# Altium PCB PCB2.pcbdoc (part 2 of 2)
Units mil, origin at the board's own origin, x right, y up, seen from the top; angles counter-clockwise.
Board outline 2299 x 1559.01 mil, 4 copper layers (Top Layer, Inner1, Inner2, Bottom Layer); 35 components, 78 nets, 930 pads, 283 vias.
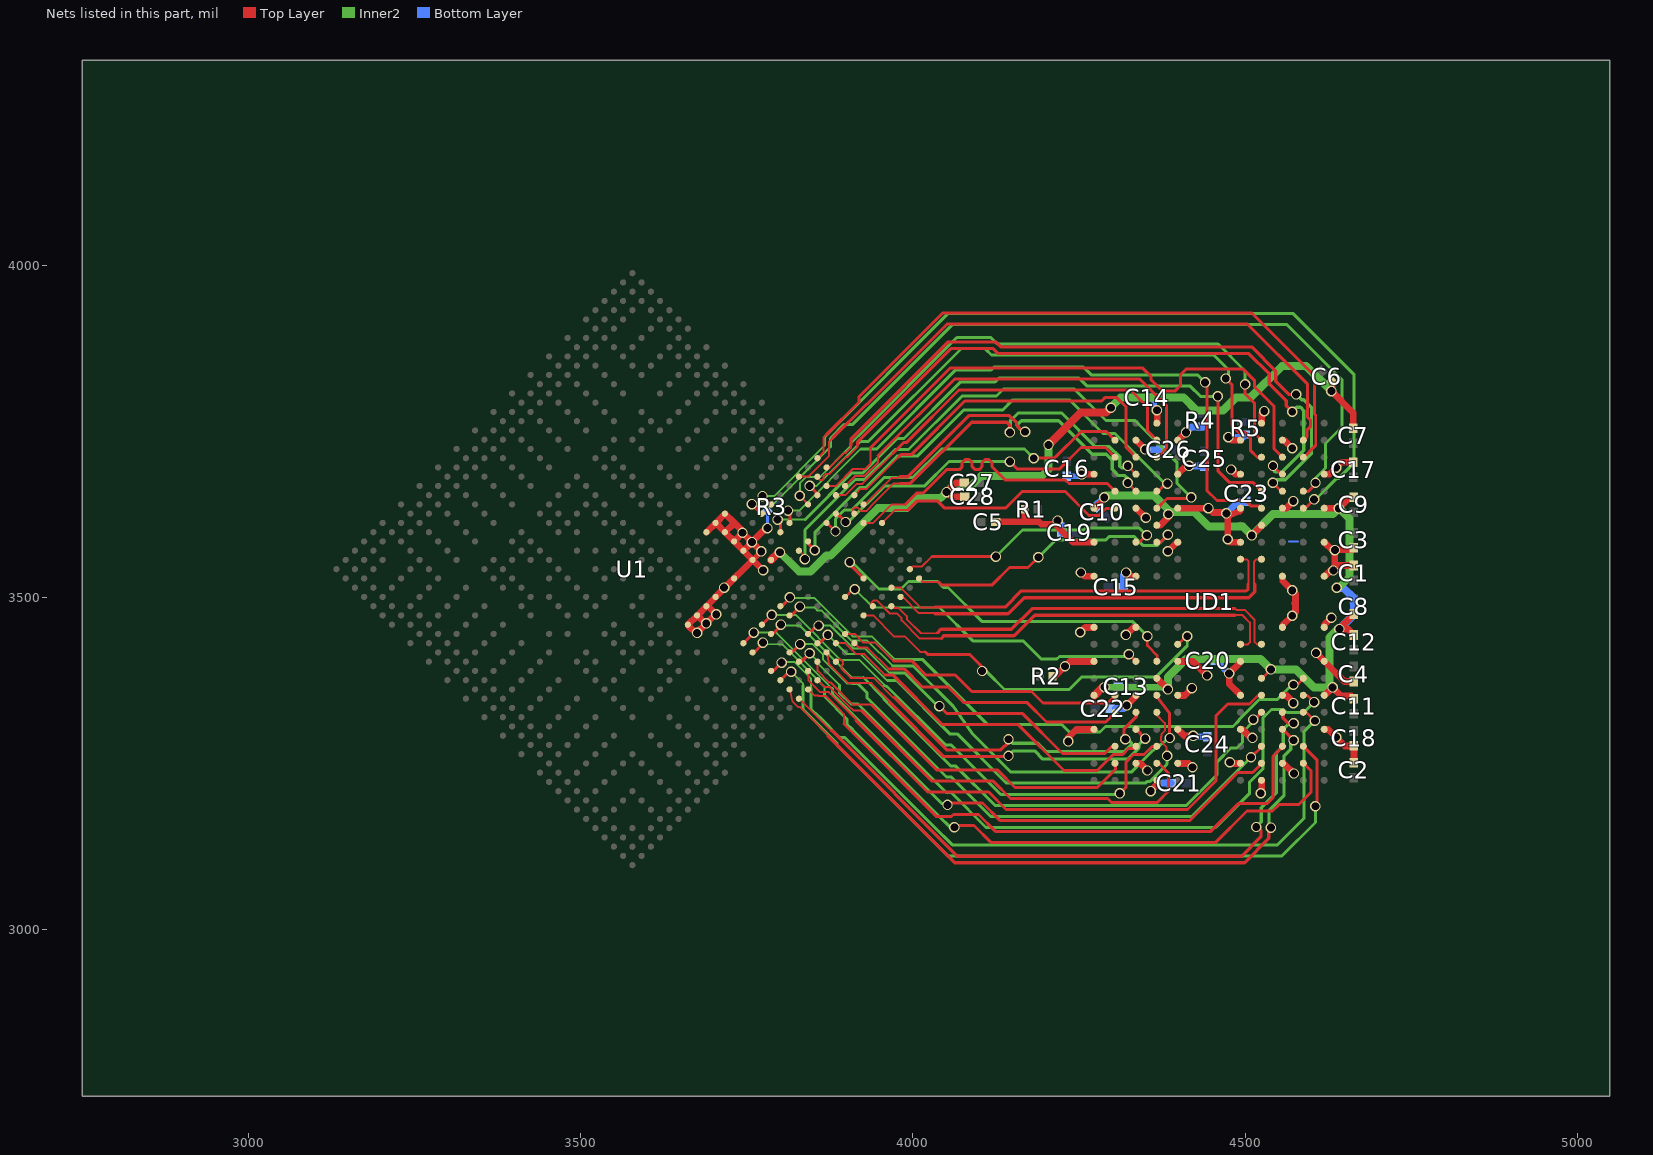
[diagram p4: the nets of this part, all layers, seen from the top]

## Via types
v1: diameter 15.75, hole 11.81, Top Layer to Bottom Layer, 283 vias

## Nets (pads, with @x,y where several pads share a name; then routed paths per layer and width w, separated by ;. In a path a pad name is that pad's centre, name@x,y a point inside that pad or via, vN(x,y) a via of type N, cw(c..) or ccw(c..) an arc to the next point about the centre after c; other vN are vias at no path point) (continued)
SCKE1-B: U1.AM27 UD1.P5 | length 596.8
  Top Layer w3: U1.AM27@3926.31,3473.4 3940.27,3473.4 3971.67,3442 3987.87,3442 4011.15,3418.72 4018.57,3418.72
  Top Layer w4: UD1.P5@4399.28,3429.75 4411.53,3442 v1(4413.08,3442)
  Top Layer w4.5: 4018.57,3418.72 4022.46,3414.83 4085.25,3414.83 4104.4,3395.68 v1(4104.4,3389.75)
  Inner2 w4.5: v1(4104.4,3389.75) 4105.35,3388.8 4111.28,3388.8 4138.08,3362 4235.59,3362 4254.59,3381 4366.35,3381 4413.08,3427.73 v1(4413.08,3442)
SCKN-A: U1.AN30 UD1.J9 | length 615.6
  Top Layer w3: U1.AN30@3981.99,3501.25 3984.6,3501.25 4008.85,3477 4032.83,3477 4033.83,3476 ; 4514.51,3520.25 4514.51,3521 4513.51,3522 4513.51,3554.43 4516.79,3557.71 UD1.J9@4525.26,3557.71
  Top Layer w5: 4033.83,3476 4143.41,3476 4167.58,3500.17 4505.66,3500.17 4514.51,3509.02 4514.51,3520.25
SCKN-B: U1.AN29 UD1.P9 | length 634
  Top Layer w3: U1.AN29@3968.06,3487.31 3970.88,3484.49 3979.12,3484.49 3991.12,3472.49 3991.12,3467.9 4012.41,3446.58 4036.41,3446.58 4037.41,3447.58 ; 4485.07,3483.76 4485.45,3483.76 4487.45,3481.76 4499.52,3481.76 4514,3467.28 4514,3434.06 4518.31,3429.75 UD1.P9@4525.26,3429.75
  Top Layer w5: 4037.41,3447.58 4042.41,3452.58 4148.28,3452.58 4179.46,3483.76 4485.07,3483.76
SCKP-A: U1.AM30 UD1.J8 | length 615.5
  Top Layer w3: U1.AM30@3968.07,3515.16 3982.01,3515.16 4012.17,3485 4032.45,3485 4033.45,3486 4033.83,3486 ; UD1.J8@4493.76,3557.71 4502.51,3557.71 4505.51,3554.71 4505.51,3522 4504.51,3521 4504.51,3520.25
  Top Layer w5: 4033.83,3486 4139.26,3486 4163.43,3510.17 4501.51,3510.17 4504.51,3513.17 4504.51,3520.25
SCKP-B: U1.AM28 UD1.P8 | length 666.5
  Top Layer w3: U1.AM28@3940.23,3487.32 3938.08,3489.46 3938.08,3492.98 3941.08,3495.98 3945.52,3495.98 3965,3476.49 3975.8,3476.49 3983.12,3469.17 3983.12,3466 4010.5,3438.58 4042.56,3438.58 ; 4485.07,3473.76 4496.2,3473.76 4507.31,3462.65 4507.31,3432.75 4504.31,3429.75 UD1.P8@4493.76,3429.75
  Top Layer w5: 4042.56,3438.58 4046.56,3442.58 4152.43,3442.58 4183.61,3473.76 4485.07,3473.76
SCS0-A: U1.AN32 UD1.H4 | length 442.4
  Top Layer w3: U1.AN32@4009.82,3529.08 4015.18,3523.72 4039.28,3523.72
  Top Layer w4.5: 4039.28,3523.72 4044,3519 4119.01,3519 4145.51,3545.5 4173.58,3545.5 v1(4189.08,3561) ; UD1.H4@4367.78,3583.3 4372.3,3583.3 4383.73,3594.73 v1(4384,3594.73)
  Inner2 w4.5: v1(4189.08,3561) 4214.98,3586.9 4290.49,3586.9 4296.09,3592.5 4332.69,3592.5 4346.89,3578.3 4367.57,3578.3 v1(4384,3594.73)
SCS0-B: U1.AK29 UD1.R4 | length 580.8
  Top Layer w4: v1(4353.08,3442) 4353.08,3428 4367.78,3413.3 UD1.R4@4367.78,3404.16
  Top Layer w4.5: v1(3905.09,3553.58) 3905.09,3550.3 U1.AK29@3926.31,3529.08
  Inner2 w4.5: v1(3905.09,3553.58) 3908.8,3549.9 3912.1,3549.9 3949,3513 3982.2,3513 3993.5,3524.3 4037.21,3524.3 4045.91,3515.6 4052.99,3515.6 4103.97,3464.62 4330.46,3464.62 v1(4353.08,3442)
SCS1-A: U1.AM32 UD1.H3 | length 407.1
  Top Layer w3: U1.AM32@3995.91,3543 4000.01,3547.09 4013.89,3547.09 4028.8,3562
  Top Layer w4.5: 4028.8,3562 v1(4125.08,3562) ; UD1.H3@4336.28,3583.3 4340.4,3583.3 4350.1,3593 4350.87,3593 4352.02,3594.15 v1(4352.27,3594.15)
  Inner2 w4.5: v1(4125.08,3562) 4164.99,3601.91 4257.01,3601.91 4260.2,3605.1 4340.9,3605.1 4351.85,3594.15 v1(4352.27,3594.15)
SCS1-B: U1.AK27 UD1.R3 | length 493.7
  Top Layer w4: U1.AK27@3898.47,3501.24 3910.13,3512.9 v1(3912.64,3512.9)
  Top Layer w4.5: v1(4325.36,3415.07) UD1.R3@4336.27,3404.16
  Inner2 w3: v1(3912.64,3512.9) 3940.13,3485.41 4040.09,3485.41
  Inner2 w4.5: 4040.09,3485.41 4090.4,3435.1 4165.9,3435.1 4193.25,3407.75 4216.85,3407.75 4220.84,3411.74 4322.03,3411.74 v1(4325.36,3415.07)
SDQ0: U1.AE28 UD1.E4 | length 729.7
  Top Layer w4.5: U1.AE28@3842.79,3584.76 3842.79,3581.33 v1(3852.53,3571.59) ; UD1.E4@4367.78,3660.07 4369.15,3660.07 4380.08,3671 4382.08,3671 4382.88,3671.8 v1(4383.13,3671.8)
  Inner2 w4.5: v1(3852.53,3571.59) 3852.53,3598.29 3920.24,3666 3929.08,3666 3976.08,3713 4006.9,3713 4076.56,3782.66 4135.44,3782.66 4150.58,3797.8 4235.71,3797.8 4286.21,3747.3 4304.22,3747.3 4328.48,3723.04 4328.48,3722.69 4379.37,3671.8 v1(4383.13,3671.8)
SDQ1: U1.AE27 UD1.F4 | length 873.7
  Top Layer w3: U1.AE27@3828.87,3570.84 3837.68,3562.03 v1(3837.68,3558.15)
  Top Layer w4.5: UD1.F4@4367.78,3634.48 4367.78,3634.7 4382.58,3649.5 4413.58,3649.5 4414.08,3650 4418,3650 v1(4419,3651)
  Inner2 w4.5: v1(3837.68,3558.15) 3837.68,3602.15 3913.81,3678.28 3928.36,3678.28 3973.08,3723 3993.56,3723 4074.26,3803.7 4126.04,3803.7 4136.64,3814.3 4243.07,3814.3 4290.62,3766.75 4334.49,3766.75 4398,3703.24 4398,3672 v1(4419,3651)
SDQ2: U1.AG32 UD1.E2 | length 464.8
  Top Layer w3: U1.AG32@3926.31,3612.6 3940.2,3612.6 3967.6,3640 3988.2,3640
  Top Layer w4.5: 3988.2,3640 4006.2,3658 4016.08,3658 4050.92,3692.84 4069.85,3692.84 4074.35,3697.34 4074.35,3703.5 4078.85,3708 4084.85,3708 4089.35,3703.5 4089.35,3697.34 4093.85,3692.84 4099.85,3692.84 4104.35,3697.34 4104.35,3703.5 4108.85,3708 4114.85,3708 4119.35,3703.5 4119.35,3697.34 4139.69,3677 4230,3677 4235,3672 4292.86,3672 UD1.E2@4304.79,3660.07
SDQ3: U1.AH33 UD1.F2 | length 398.6
  Top Layer w3: U1.AH33@3954.15,3612.59 3973.84,3632.28 3993.24,3632.28
  Top Layer w4.5: 3993.24,3632.28 4006.92,3645.96 4036.84,3645.96 4047.43,3635.37 4140.46,3635.37 4165.3,3660.21 4229.03,3660.21 4265.33,3623.91 4279.99,3623.91 4290.56,3634.48 UD1.F2@4304.79,3634.48
SDQ4: U1.AE30 UD1.B2 | length 529.9
  Top Layer w4.5: U1.AE30@3870.63,3612.6 3870.89,3612.6 v1(3883.72,3599.77) ; v1(4182.08,3710) 4213.08,3710 4253.08,3750 4291.63,3750 UD1.B2@4304.79,3736.84
  Inner2 w4.5: v1(3883.72,3599.77) 3883.72,3618.87 3896.95,3632.1 3908.11,3632.1 3956.73,3680.72 3999.81,3680.72 4043.09,3724 4168.08,3724 v1(4182.08,3710)
SDQ5: U1.AD32 UD1.B4 | length 600.8
  Top Layer w3: U1.AD32@3884.55,3654.36 3898.5,3654.36 3915.43,3671.29 3924.24,3671.29 3969.95,3717
  Top Layer w4.5: 3969.95,3717 3986.95,3734 3991.08,3734 4069.58,3812.5 4327.5,3812.5 4353,3787 4353,3751.62 UD1.B4@4367.78,3736.84
SDQ6: U1.AE31 UD1.C2 | length 487.4
  Top Layer w4.5: U1.AE31@3884.55,3626.52 3886.48,3626.52 v1(3899,3614) ; v1(4146.08,3705) 4157.58,3693.5 4220.57,3693.5 4253.03,3725.96 4290.08,3725.96 UD1.C2@4304.79,3711.25
  Inner2 w4.5: v1(3899,3614) 3903,3614 3957,3668 4017.4,3668 4054.4,3705 v1(4146.08,3705)
SDQ7: U1.AD33 UD1.C4 | length 656.3
  Top Layer w3: U1.AD33@3898.47,3668.27 3913.43,3683.22 3927.22,3683.22 3947.8,3703.8 3947.8,3714.06
  Top Layer w4.5: 3947.8,3714.06 4062.74,3829 4342,3829 4382,3789 4382,3725.47 UD1.C4@4367.78,3711.25
SDQ8: U1.AC27 UD1.E9 | length 973.9
  Top Layer w4.5: v1(3796.67,3617.55) 3801.03,3613.19 U1.AC27@3801.03,3598.68 ; v1(4459,3803) 4459,3691 4476.89,3673.11 4512.22,3673.11 UD1.E9@4525.26,3660.07
  Inner2 w3: v1(3796.67,3617.55) 3837.63,3617.55
  Inner2 w4.5: 3837.63,3617.55 3908.08,3688 3925,3688 3976.53,3739.53 3986.75,3739.53 4072.22,3825 4124,3825 4129.8,3830.8 4249.91,3830.8 4261.71,3819 4417,3819 4417.55,3818.45 4417.78,3818.45 4433.23,3803 v1(4459,3803)
SDQ9: U1.AC28 UD1.F9 | length 1004.1
  Top Layer w4.5: v1(3812.19,3631.19) 3814.95,3628.43 U1.AC28@3814.95,3612.6 ; v1(4440,3824) 4442.58,3821.42 4442.58,3661.51 4457.77,3646.32 4500.3,3646.32 4508.62,3638 4521.74,3638 UD1.F9@4525.26,3634.48
  Inner2 w3: v1(3812.19,3631.19) 3829.09,3631.19 3921.9,3724
  Inner2 w4.5: 3921.9,3724 3945.81,3724 4064.81,3843 4118,3843 4122.3,3847.3 4256.75,3847.3 4268.55,3835.5 4428.5,3835.5 v1(4440,3824)
SDQ10: U1.AC30 UD1.B9 | length 936.1
  Top Layer w3: v1(3829.98,3653.51) 3842.79,3640.7 U1.AC30@3842.79,3640.44
  Top Layer w4.5: v1(4500.08,3821) 4500.08,3807 4514.08,3793 4514.08,3748.02 UD1.B9@4525.26,3736.84
  Inner2 w3: v1(3829.98,3653.51) 3829.98,3672.41 3839.57,3682 3860.51,3682 3906.26,3727.74 3906.26,3731.55 3919.08,3744.37
  Inner2 w4.5: 3919.08,3744.37 4066.31,3891.6 4117.4,3891.6 4127.25,3881.75 4459.67,3881.75 4500.08,3841.34 v1(4500.08,3821)
SDQ11: U1.AC31 UD1.C9 | length 913.6
  Top Layer w4.5: v1(3844.82,3668.36) 3856.71,3656.47 U1.AC31@3856.71,3654.36 ; v1(4471,3830) 4480.08,3820.92 4480.08,3759 4490.08,3749 4500.08,3749 4508.08,3741 4508.08,3722 4518.83,3711.25 UD1.C9@4525.26,3711.25
  Inner2 w3: v1(3844.82,3668.36) 3855.36,3668.36 3922,3735
  Inner2 w4.5: 3922,3735 3933.05,3735 4073.15,3875.1 4108.26,3875.1 4109.36,3874 4109.72,3874 4118.47,3865.25 4452.83,3865.25 4475,3843.08 4475,3834 v1(4471,3830)
SDQ12: U1.AA33 UD1.C11 | length 1026.4
  Top Layer w3: U1.AA33@3856.71,3710.03 3866,3719.32 3866,3741.5 3869.7,3745.2
  Top Layer w4.5: 3869.7,3745.2 3919.14,3794.64 3919.14,3802.62 4045.03,3928.51 4510.28,3928.51 4604.68,3834.11 4604.68,3776.32 4606.47,3774.53 4606.47,3729.47 UD1.C11@4588.25,3711.25
SDQ13: U1.AA31 UD1.B11 | length 1001.5
  Top Layer w3: U1.AA31@3828.87,3682.19 3842.76,3682.19 3874,3713.43 3874,3735 3879,3740
  Top Layer w4.5: 3879,3740 3929.84,3790.84 3930.7,3790.84 4051.87,3912.01 4503.44,3912.01 4594.32,3821.13 4594.32,3771.31 4598.82,3766.81 4598.82,3758.05 4593,3752.23 4593,3741.59 UD1.B11@4588.25,3736.84
SDQ14: U1.AA28 UD1.F11 | length 1305.8
  Top Layer w4.5: v1(3773.85,3653.07) 3786.48,3640.44 U1.AA28@3787.11,3640.44 ; UD1.F11@4588.25,3634.48 4590.48,3634.48 v1(4604,3648)
  Inner2 w3: v1(3773.85,3653.07) 3791.54,3653.07 3867,3728.53 3867,3728.9
  Inner2 w4.5: 3867,3728.9 3867,3741.62 4053.38,3928 4572.01,3928 4664.3,3835.71 4664.3,3703.72 4660,3699.42 4660,3698.77 4659.75,3698.51 4640.49,3679.25 4637.17,3679.25 4605.92,3648 v1(4604,3648)
SDQ15: U1.AA27 UD1.E11 | length 1263.1
  Top Layer w4.5: v1(3757.78,3640.88) 3772.14,3626.52 U1.AA27@3773.19,3626.52 ; UD1.E11@4588.25,3660.07 4595.15,3660.07 4605.08,3670 4605.08,3672 v1(4606.08,3673)
  Inner2 w3: v1(3757.78,3640.88) 3761.66,3637 3786.08,3637 3876,3726.92
  Inner2 w4.5: 3876,3726.92 3876,3740.01 3896.99,3761 3909.72,3761 4060.22,3911.5 4562.58,3911.5 4645.98,3828.1 4645.98,3756.98 4621.1,3732.1 4621.1,3695.4 4606.08,3680.38 v1(4606.08,3673)
SDQ16: U1.AM25 UD1.U2 | length 454
  Top Layer w3: U1.AM25@3898.47,3445.56 3912.36,3445.56 3924.92,3433 3942.7,3433 3970.7,3405
  Top Layer w4.5: 3970.7,3405 3998.34,3405 4019.51,3383.83 4063.91,3383.83 4088.77,3359 4178.62,3359 4195.89,3341.73 4293.54,3341.73 UD1.U2@4304.79,3352.98
SDQ17: U1.AN25 UD1.V2 | length 447.5
  Top Layer w3: U1.AN25@3912.39,3431.64 3919.03,3425 3931.59,3425 3963.59,3393
  Top Layer w4.5: 3963.59,3393 3987,3393 4014,3366 4053.06,3366 4077.1,3342 4172.28,3342 4201.28,3313 4290.4,3313 UD1.V2@4304.79,3327.39
SDQ18: U1.AH23 UD1.U4 | length 775.2
  Top Layer w4.5: U1.AH23@3814.95,3473.4 3816.98,3473.4 v1(3830.24,3486.7) ; UD1.U4@4367.78,3352.98 4367.51,3351.11 4386.65,3325.61 v1@4386.65,3288.95
  Inner2 w3: v1(3830.24,3486.7) 3831.52,3485.42 3851.58,3485.42 3856,3481 3862.04,3481 3907.04,3436 3931,3436 3969.6,3397.4
  Inner2 w4.5: 3969.6,3397.4 4000.44,3397.4 4060.28,3337.56 4089.7,3295.61 4147.82,3237.49 4328.8,3237.49 4360.17,3268.86 4382.97,3285.95 4385.94,3288.92 v1(4386.65,3288.92)
SDQ19: U1.AK23 UD1.Y2 | length 551.2
  Top Layer w4.5: U1.AK23@3842.79,3445.56 3855.26,3458.03 v1(3858.17,3458.03) ; v1(4040.08,3337) 4051.58,3325.5 4165.44,3325.5 4225.3,3265.64 4288.98,3265.64 4299.55,3276.21 UD1.Y2@4304.79,3276.21
  Inner2 w3: v1(3858.17,3458.03) 3876.18,3458.03 3910.21,3424 3928,3424 3965.4,3386.6
  Inner2 w4.5: 3965.4,3386.6 3987.9,3386.6 4037.5,3337 v1(4040.08,3337)
SDQ20: U1.AL23 UD1.V4 | length 723.1
  Top Layer w3: UD1.V4@4365.76,3325.09 4379.47,3311.37 4379.47,3300.01 4374.08,3294.62 4374.08,3291.7 4373.26,3290.88 4373.26,3284.75 4375.46,3282.55 4375.46,3281.87 4382.08,3275.25 4382.08,3262.66 v1(4382.74,3262)
  Top Layer w4.5: U1.AL23@3856.71,3431.64 3859.64,3431.64 v1(3872,3444)
  Inner2 w3: v1(3872,3444) 3901,3415 3922.01,3415 3961.61,3375.4
  Inner2 w4.5: 3961.61,3375.4 3975.4,3375.4 4055.6,3295.2 4066.77,3295.2 4140.98,3220.99 4349.91,3220.99 4352.17,3223.25 4356.48,3223.25 4382.74,3249.51 v1(4382.74,3262)
SDQ21: U1.AM22 UD1.AA2 | length 554.9
  Top Layer w3: U1.AM22@3856.72,3403.81 3856.72,3389.91 3873.81,3372.82 3876.17,3372.82 3909.99,3339 3937.99,3339
  Top Layer w4.5: 3937.99,3339 4036.49,3240.5 4127.91,3240.5 4153.95,3214.46 4277.67,3214.46 4304.79,3241.58 UD1.AA2@4304.79,3250.62
SDQ22: U1.AN21 UD1.AA4 | length 661.8
  Top Layer w3: U1.AN21@3856.71,3375.97 3867.36,3365.32 3875.18,3365.32 3907.5,3333 3908.1,3333 3911.1,3330 3923.08,3330
  Top Layer w4.5: 3923.08,3330 4029.08,3224 4121.07,3224 4147.11,3197.96 4293.25,3197.96 4299.21,3192 4368,3192 4385,3209 4385,3236 4370.38,3250.62 UD1.AA4@4367.78,3250.62
SDQ23: U1.AG21 UD1.Y4 | length 765.2
  Top Layer w4.5: U1.AG21@3773.19,3459.48 3787.66,3473.95 v1(3787.66,3474.25) ; v1(4311.6,3205.6) 4321.08,3215.08 4321.08,3253 4332.08,3264 4348.08,3264 4360.29,3276.21 UD1.Y4@4367.78,3276.21
  Inner2 w3: v1(3787.66,3474.25) 3823.54,3474.25 3891.79,3406 3920,3406 3956.9,3369.1 3956.9,3368.09
  Inner2 w4.5: 3956.9,3368.09 3961.12,3366.34 4048.76,3278.7 4057.7,3278.7 4132.49,3203.91 4309.91,3203.91 v1(4311.6,3205.6)
SDQ24: U1.AG19 UD1.AA9 | length 946.4
  Top Layer w4.5: U1.AG19@3745.36,3431.64 3759.3,3445.58 3759.3,3446.2 v1(3760.6,3447.5) ; v1(4052.23,3188.15) 4055.08,3191 4105.01,3191 4131.05,3164.96 4417.05,3164.96 4489.09,3237 4511.64,3237 UD1.AA9@4525.26,3250.62
  Inner2 w3: v1(3760.6,3447.5) 3794.58,3447.5 3879,3363.08
  Inner2 w4.5: 3879,3363.08 3879,3355.1 4043.6,3190.5 4046,3190.5 4048.35,3188.15 v1(4052.23,3188.15)
SDQ25: U1.AH19 UD1.AA11 | length 1065.7
  Top Layer w4.5: U1.AH19@3759.28,3417.72 3761.29,3417.72 3773.2,3429.63 3773.2,3431.1 v1(3774.5,3432.4) ; v1(4062.6,3154.7) 4065.46,3154.7 4068.01,3157.25 4092.08,3157.25 4117.37,3131.96 4455.96,3131.96 4503,3179 4541.43,3179 4551.43,3189 4581,3189 4599,3207 4599,3239.87 UD1.AA11@4588.25,3250.62
  Inner2 w3: v1(3774.5,3432.4) 3776.87,3430.03 3803.41,3430.03 3867,3366.44 3867,3359.01
  Inner2 w4.5: 3867,3359.01 3867,3351.22 3901,3317.22 3901,3309.9 3909.67,3301.23 3909.67,3301.09 4039.11,3171.65 4039.25,3171.65 4056.2,3154.7 v1(4062.6,3154.7)
SDQ26: U1.AK19 UD1.V11 | length 1140.5
  Top Layer w4.5: U1.AK19@3787.11,3389.88 3790.01,3389.88 v1(3802.49,3402.36) ; UD1.V11@4588.25,3327.39 4592.69,3327.39 v1(4605.08,3315)
  Inner2 w3: v1(3802.49,3402.36) 3803.79,3403.66 3821.29,3403.66 3847,3377.95 3847,3364
  Inner2 w4.5: 3847,3364 3847,3332.26 3858.51,3320.75 3859.15,3320.75 3890.48,3289.42 3898,3289.42 4032.27,3155.15 4032.41,3155.15 4059.46,3128.1 4548.78,3128.1 4589.08,3168.4 4589.08,3299 v1(4605.08,3315)
SDQ27: U1.AL19 UD1.Y11 | length 1093.8
  Top Layer w4.5: U1.AL19@3801.03,3375.97 3813.61,3388.55 v1(3816.97,3388.55) ; UD1.Y11@4587.73,3276.48 4608,3256.21 4608,3188.18 v1(4605.95,3186.13)
  Inner2 w3: v1(3816.97,3388.55) 3835.1,3370.42 3835.1,3367.59
  Inner2 w4.5: 3835.1,3367.59 3835.1,3331.7 3886.33,3280.47 3886.33,3277.75 4025.45,3138.63 4025.57,3138.63 4052.62,3111.6 4555.62,3111.6 4605.95,3161.93 v1(4605.95,3186.13)
SDQ28: U1.AM21 UD1.U9 | length 906.3
  Top Layer w3: U1.AM21@3842.79,3389.88 3842.79,3376 3860.97,3357.82 3873.68,3357.82 3914.74,3316.76 3914.74,3315
  Top Layer w4.5: 3914.74,3315 4022.24,3207.5 4114.23,3207.5 4140.27,3181.46 4413.28,3181.46 4456.08,3224.26 4456.08,3322.08 4474.06,3340.06 4506.75,3340.06 4519.67,3352.98 UD1.U9@4525.26,3352.98
SDQ29: U1.AL21 UD1.U11 | length 1054.3
  Top Layer w4.5: U1.AL21@3828.87,3403.81 3832.23,3403.81 v1(3844.81,3416.39) ; UD1.U11@4588.25,3352.98 4594.1,3352.98 v1(4604.08,3343)
  Inner2 w3: v1(3844.81,3416.39) 3855.98,3405.22 3855.98,3402.39 3890,3368.37
  Inner2 w4.5: 3890,3368.37 3890,3357 3907,3340 3917.44,3340 4050.44,3207 4057.76,3207 4110.35,3154.41 4455.89,3154.41 4506.4,3204.92 4506.4,3221.89 4526.8,3242.29 4526.8,3318.88 4539.92,3332 4558,3332 4563,3327 4588.08,3327 v1(4604.08,3343)
SDQ30: U1.AK21 UD1.Y9 | length 875.2
  Top Layer w4: v1(4509.03,3259.98) UD1.Y9@4525.26,3276.21
  Top Layer w4.5: U1.AK21@3814.95,3417.72 3817.85,3417.72 v1(3830.33,3430.2)
  Inner2 w3: v1(3830.33,3430.2) 3849.31,3430.2 3865,3414.51 3865,3407 3901,3371 3908.19,3371
  Inner2 w4.5: 3908.19,3371 3917.1,3371 3930.8,3357.3 3930.8,3349.98 4050.69,3230.09 4058.01,3230.09 4117.19,3170.91 4419.96,3170.91 v1(4509.03,3259.98)
SDQ31: U1.AH21 UD1.V9 | length 938.7
  Top Layer w4.5: U1.AH21@3787.11,3445.56 3789.13,3445.56 3801.5,3457.93 v1(3801.5,3459.5) ; v1(4512.48,3316.57) 4514.44,3316.57 UD1.V9@4525.26,3327.39
  Inner2 w3: v1(3801.5,3459.5) 3802.52,3458.48 3829.52,3458.48 3908,3380 3926,3380
  Inner2 w4.5: 3926,3380 3956.35,3349.65 3956.35,3347.77 4057.53,3246.59 4064.85,3246.59 4124.03,3187.41 4411.57,3187.41 4458.08,3233.92 4458.08,3253.35 4478.44,3273.71 4487.91,3273.71 4496.25,3282.05 4496.25,3297.38 4512.48,3313.61 v1(4512.48,3316.57)
SDQM0: U1.AE33 UD1.C3 | length 558
  Top Layer w3: U1.AE33@3912.39,3654.36 3912.39,3654.54 3921.64,3663.79 3930.57,3663.79 3978.39,3711.61
  Top Layer w4.5: 3978.39,3711.61 3982.08,3715.3 3997.71,3715.3 4078.41,3796 4255.76,3796 4256.01,3796.25 4284.25,3796.25 4289.7,3801.7 4306.39,3801.7 4321.08,3787.01 4321.08,3726.45 UD1.C3@4336.28,3711.25
SDQM1: U1.AC32 UD1.C10 | length 912.2
  Top Layer w3: U1.AC32@3870.63,3668.28 3884.53,3668.28 3909.98,3693.74 3928.74,3693.74 3936.32,3701.32 3936.32,3723.12
  Top Layer w4.5: 3936.32,3723.12 3936.32,3725.92 4055.9,3845.5 4346.28,3845.5 4358.58,3833.2 4358.58,3827.91 4375.06,3811.43 4395.09,3811.43 4403.07,3819.41 4403.07,3835.78 4411.29,3844 4497.42,3844 4514,3827.42 4514,3817.82 4544,3787.82 4544,3724.01 UD1.C10@4556.76,3711.25
SDQM2: U1.AM24 UD1.Y3 | length 546.1
  Top Layer w3: U1.AM24@3884.55,3431.64 3898.45,3431.64 3915.08,3415 3927,3415 3958,3384
  Top Layer w4.5: 3958,3384 3969.74,3384 4044.74,3309 4158.6,3309 4227.55,3240.05 4277.74,3240.05 4301.69,3264 4315.82,3264 4324.82,3273 4333.07,3273 UD1.Y3@4336.28,3276.21
SDQM3: U1.AN20 UD1.Y10 | length 903
  Top Layer w3: U1.AN20@3842.79,3362.05 3851.86,3352.98 3857.32,3352.98 3858.48,3351.82 3869.43,3351.82 3883.35,3337.9 3883.48,3337.9 3890.8,3330.58 3890.8,3330.45 3896.4,3324.85 3896.4,3309.92
  Top Layer w4.5: 3896.4,3309.92 4035.32,3171 4058.42,3171 4061.17,3173.75 4098.92,3173.75 4124.21,3148.46 4448.46,3148.46 4490,3190 4533,3190 4542,3199 4542,3261.45 UD1.Y10@4556.76,3276.21
SDQS0N: U1.AF33 UD1.E3 | length 565.1
  Top Layer w3: U1.AF33@3926.31,3640.43 3928.31,3640.43 3967.88,3680 3976.27,3680 3977.27,3681 3979.62,3681 3980.62,3682 3981,3682
  Top Layer w3.8: v1(4323.48,3672.87) UD1.E3@4336.28,3660.07
  Top Layer w5: 3981,3682 3992.35,3682 4084.56,3774.21 4145.37,3774.21 4156.15,3763.43 4156.15,3759.28 4164.11,3751.32 4164.68,3751.31 4166.05,3749.95 4166.32,3749.74 v1(4169.14,3749.74)
  Inner2 w5: v1@4169.12,3749.76 4165.9,3749.76 4158.25,3757.41 4158.25,3761.26 4163.54,3766.55 4219.36,3766.55 4269.86,3716.05 4291.26,3716.05 4300.08,3707.23 4300.08,3693.32 4309.5,3683.9 4319.17,3683.9 4323.48,3679.59 v1(4323.48,3672.87)
SDQS0P: U1.AF32 UD1.D3 | length 576.6
  Top Layer w3: U1.AF32@3912.39,3626.53 3909.95,3628.97 3909.95,3633.09 3912.46,3635.6 3916.95,3635.6 3921.94,3630.61 3930.43,3630.61 ; 3930.43,3630.66 3936.13,3636.36 3936.13,3636.93 3971.2,3672 3981,3672
  Top Layer w3.8: v1(4323.48,3698.45) UD1.D3@4336.28,3685.66
  Top Layer w5: 3981,3672 3996.5,3672 4088.71,3764.21 4141.22,3764.21 4146.15,3759.28 v1(4146.15,3748.77)
  Inner2 w5: v1(4146.15,3748.77) 4146.75,3749.37 4146.75,3766.03 4158.77,3778.05 4224.13,3778.05 4274.63,3727.55 4296.03,3727.55 4311.58,3712 4311.58,3698.09 4314.27,3695.4 4321.48,3695.4 4323.48,3697.4 v1(4323.48,3698.45)
SDQS1N: U1.AB33 UD1.E10 | length 1030.8
  Top Layer w3: U1.AB33@3870.63,3696.11 3875.11,3696.11 3897,3718 3899.39,3718 3906.9,3725.51 3906.9,3729.75
  Top Layer w3.8: v1(4542.08,3673) 4555.01,3660.07 UD1.E10@4556.76,3660.07
  Top Layer w5: 3906.9,3729.75 3906.9,3738.59 4053.31,3885 4125,3885 4132.5,3877.5 4510,3877.5 4546.41,3841.09 4546.41,3825.59 4566,3806 v1(4577,3806)
  Inner2 w5: v1(4542.08,3673) 4546.9,3677.8 4560.66,3677.8 4600.12,3717.26 4600.12,3786.24 4588.39,3797.97 4585.03,3797.97 v1(4577,3806)
SDQS1P: U1.AB32 UD1.D10 | length 1034
  Top Layer w3: U1.AB32@3856.72,3682.19 3856.72,3680.98 3860.75,3676.95 3863.77,3676.95 3865.9,3679.08 3865.9,3683.3 3868.7,3686.1 3874.57,3686.1 3900.47,3712 3901.88,3712 3916.9,3727.02 3916.9,3729.75
  Top Layer w3.8: v1(4542.14,3698.52) 4555,3685.66 UD1.D10@4556.76,3685.66
  Top Layer w5: 3916.9,3729.75 3916.9,3734.44 4057.46,3875 4120.85,3875 4128.35,3867.5 4505.85,3867.5 4536.41,3836.94 4536.41,3822.07 4562,3796.48 4562,3789 v1(4571,3780)
  Inner2 w4.1: v1@4542.12,3692.29 v1(4542.14,3698.52)
  Inner2 w5: v1(4542.14,3698.52) 4542.14,3692.27 4545.11,3689.3 4555.89,3689.3 4588.62,3722.03 4588.62,3781.47 4583.62,3786.47 4577.47,3786.47 v1(4571,3780)
SDQS2N: U1.AN23 UD1.V3 | length 595.5
  Top Layer w3: U1.AN23@3884.55,3403.81 3887.74,3407 3891.99,3407 3894.99,3404 3894.99,3399.75 3892.75,3397.51 3892.75,3393.26 3906.41,3379.6 3941.08,3379.6 3970.86,3349.82 3972.26,3349.82 3972.53,3349.55
  Top Layer w5: 3972.53,3349.55 4051.09,3270.99 4132.56,3270.99 4144.08,3282.51 v1(4144.08,3287) ; v1(4320.08,3287) 4318,3289.08 4318,3303 4336.28,3321.28 UD1.V3@4336.28,3327.39
  Inner2 w5: v1(4144.08,3287) 4150.08,3281 4188,3281 4200.26,3268.74 4319.06,3268.74 4328.93,3278.61 4328.93,3282 4323.93,3287 v1(4320.08,3287)
SDQS2P: U1.AM23 UD1.W3 | length 595.6
  Top Layer w3: U1.AM23@3870.63,3417.72 3874.24,3400.17 3902.81,3371.6 3937.76,3371.6 3965.46,3343.9 3965.46,3342.47
  Top Layer w5: 3965.46,3342.47 4046.94,3260.99 4143.07,3260.99 v1(4144.08,3262) ; UD1.W3@4336.28,3301.8 v1(4349.94,3288.14)
  Inner2 w5: v1(4144.08,3262) 4151.58,3269.5 4183.23,3269.5 4195.49,3257.24 4323.83,3257.24 4340.43,3273.84 4340.43,3278.63 v1(4349.94,3288.14)
SDQS3N: U1.AN19 UD1.V10 | length 1035.5
  Top Layer w3: U1.AN19@3828.87,3348.13 3877.27,3299.69 3878.69,3299.69
  Top Layer w5: 3878.69,3299.69 4067.17,3111.21 4495.13,3111.21 4524,3140.08 4524,3150 4519,3155 v1(4517,3155) ; UD1.V10@4556.76,3327.39 4556.58,3327.21 4556.58,3319.42 4564.92,3311.08 v1(4573.07,3311.08)
  Inner2 w5: v1(4517,3155) 4524.57,3162.57 4524.57,3183.98 4547.08,3206.49 4547.08,3266.38 4557.38,3276.68 4557.38,3302.17 4566.29,3311.08 v1(4573.07,3311.08)
SDQS3P: U1.AM19 UD1.W10 | length 1040.5
  Top Layer w3: U1.AM19@3814.95,3362.04 3818.62,3344.49 3827.81,3335.3 3830.36,3335.3 3872.71,3292.93 3872.71,3291.52
  Top Layer w5: 3872.71,3291.52 4063.02,3101.21 4499.28,3101.21 4535.92,3137.85 4535.92,3150.92 v1(4539,3154) ; UD1.W10@4556.76,3301.8 v1(4573.07,3285.49)
  Inner2 w5: v1(4539,3154) 4536.07,3156.93 4536.07,3179.21 4558.58,3201.72 4558.58,3261.61 4568.88,3271.91 4568.88,3281.3 v1(4573.07,3285.49)
SRST: U1.AG23 UD1.T11 | length 911.1
  Top Layer w4: v1(4572.85,3369.16) 4574.68,3370.99 4580.67,3370.99 UD1.T11@4588.25,3378.57
  Top Layer w4.5: U1.AG23@3801.03,3487.32 3802.62,3487.32 3815.07,3499.77 v1(3815.09,3500.58)
  Inner2 w3: v1(3815.09,3500.58) 3815.57,3500.1 3816.1,3500.1 3816.37,3499.83 3851.69,3499.83 3909.52,3442 3938,3442 3972.6,3407.4
  Inner2 w4.5: 3972.6,3407.4 4014.25,3407.4 4112.15,3309.5 4223.86,3309.5 4235.47,3297.89 4281.79,3297.89 4290.2,3306.3 4481.83,3306.3 4490.59,3315.06 4490.59,3316.05 4521.54,3347 4548.52,3347 4570.68,3369.16 v1(4572.85,3369.16)
VCC-DRAM: C1.1 C2.1 C3.2 C4.2 C5.2 C14.1 C15.1 C16.2 C17.2 C18.2 C19.1 C20.2 C21.2 C22.2 C23.2 C24.2 C25.2 C26.2 R1.2 R2.2 R3.2 R4.2 R5.2 U1.AA24 U1.AB24 U1.AC17 U1.AC18 U1.AC19 U1.AC20 U1.AC22 U1.AC24 U1.W23 U1.W24 U1.W25 U1.Y24 UD1.A4 UD1.A9 UD1.AA3 UD1.AA5 UD1.AA8 UD1.AA10 UD1.AB4 UD1.AB9 UD1.B3 UD1.B5 UD1.B8 UD1.B10 UD1.D1 UD1.D5 UD1.D8 UD1.D12 UD1.F3 UD1.F5 UD1.F8 UD1.F10 UD1.H1 UD1.H5 UD1.H8 UD1.H12 UD1.K1 UD1.K3 UD1.K10 UD1.K12 UD1.N1 UD1.N3 UD1.N10 UD1.N12 UD1.R1 UD1.R5 UD1.R8 UD1.R12 UD1.U3 UD1.U5 UD1.U8 UD1.U10 UD1.W1 UD1.W5 UD1.W8 UD1.W12 | length 2586.3
  Top Layer w8: U1.AC24@3759.28,3556.93 v1(3772,3569.65)
  Top Layer w10: U1.AC19@3689.67,3487.32 U1.AC18@3675.76,3473.41 ; U1.W23@3689.68,3598.68 U1.W24@3703.6,3612.6 ; v1(3772,3569.65) v1(3757.86,3583.79) ; v1(3774.83,3541.37) U1.AC24@3759.28,3556.91 ; v1(3781.12,3604.84) 3778.9,3604.84 v1(3757.86,3583.79) ; C5.2@4125,3614 4125.16,3614.16 4176.84,3614.16 ; R1.2@4168.49,3633 4169,3632.49 4169,3622 4176.84,3614.16 ; R2.2@4210.33,3382.29 4214.37,3382.29 v1(4229.08,3397) 4236.24,3404.16 UD1.R1@4273.29,3404.16 ; v1(4233.97,3283.71) 4234,3289.7 4246.1,3301.8 UD1.W1@4273.29,3301.8 ; v1(4252,3448) 4259.34,3455.34 UD1.N1@4273.29,3455.34 ; v1(4253.08,3538) 4258.96,3532.12 UD1.K1@4273.29,3532.12 ; v1(4253.97,3685.66) 4272.5,3685.66 UD1.D1@4272.77,3685.93 ; UD1.H1@4273.29,3583.3 4241.6,3583.3 4218,3606.9 v1(4218,3616.16) 4212.49,3610.65 4193.41,3610.65 4189.9,3614.16 4176.84,3614.16 ; v1(4320.76,3444) 4332.1,3455.34 UD1.N3@4336.28,3455.34 ; v1(4321.08,3538) 4326.96,3532.12 UD1.K3@4336.28,3532.12 ; v1(4322.08,3338) 4336.28,3352.2 UD1.U3@4336.28,3352.98 ; UD1.AA3@4336.28,3250.62 4342.47,3250.62 v1(4353.08,3240.01) ; UD1.F3@4336.28,3634.48 4350.09,3620.67 4350.6,3620.67 v1(4350.78,3620.49) ; UD1.B3@4336.28,3736.84 v1(4349.94,3723.18) ; v1(4358.08,3209) 4367.78,3218.7 UD1.AB4@4367.78,3225.03 ; v1(4367.5,3782.2) 4367.78,3781.92 UD1.A4@4367.78,3762.43 ; v1(4384,3570) 4397.3,3583.3 UD1.H5@4399.28,3583.3 ; UD1.AA5@4399.28,3250.62 4415.38,3250.62 v1(4421,3245) ; UD1.W5@4399.28,3301.8 4409.08,3292 v1(4422,3292) ; UD1.U5@4399.28,3352.98 4409.28,3352.98 4420.08,3363.78 v1(4420.08,3364) ; UD1.R5@4399.28,3404.16 4421.82,3404.16 v1(4443,3382.98) ; UD1.F5@4399.28,3634.48 4444.48,3634.48 v1(4445,3635) 4451.7,3628.3 4470.8,3628.3 v1(4472.07,3627.03) ; UD1.D5@4399.28,3685.66 4399.28,3686.69 4410.96,3698.37 v1(4415.96,3698.37) ; UD1.B5@4399.28,3736.84 v1(4411.21,3748.77) ; v1(4475.09,3741.8) 4480.05,3736.84 UD1.B8@4493.76,3736.84 ; v1(4477.31,3252.42) 4479.11,3250.62 UD1.AA8@4493.76,3250.62 ; v1(4479.08,3693) 4486.42,3685.66 UD1.D8@4493.76,3685.66 ; UD1.W8@4493.76,3301.8 4496.2,3301.8 4508.96,3289.04 v1(4511.3,3289.04) ; UD1.U8@4493.76,3352.98 4476.08,3370.66 v1(4476.08,3386) 4493.76,3403.68 UD1.R8@4493.76,3404.16 ; UD1.H8@4493.76,3583.3 4478.78,3583.3 v1(4474.08,3588) 4474.08,3625.02 v1(4472.07,3627.03) ; UD1.F8@4493.76,3634.48 4492.14,3630.57 4477.83,3624.64 v1(4472.07,3627.03) ; v1(4523.64,3205.78) 4525.26,3207.4 UD1.AB9@4525.26,3225.03 ; UD1.A9@4525.26,3762.43 4525.26,3777.26 v1(4529,3781) ; UD1.AA10@4556.76,3250.62 4558.38,3250.62 v1(4573.5,3235.5) ; UD1.U10@4556.76,3352.98 4562.5,3352.98 4572.5,3342.98 v1(4572.5,3341.53) ; UD1.N10@4556.76,3455.34 4556.76,3458.76 v1(4571,3473) 4576,3477.99 4576.01,3505.99 v1(4571,3511) 4556.76,3525.24 UD1.K10@4556.76,3532.12 ; UD1.F10@4556.76,3634.48 4561.75,3634.48 v1(4572.69,3645.42) ; UD1.B10@4556.76,3736.84 4559.24,3736.84 v1(4571.08,3725) ; v1(4606.95,3416.96) 4619.48,3404.43 UD1.R12@4619.23,3404.43 4649.66,3374 C4.2@4664,3374 ; UD1.W12@4619.75,3301.8 4625.2,3301.8 v1(4637,3290) 4650,3277 C18.2@4664,3277 C2.1@4664,3251.5 ; UD1.N12@4619.75,3455.34 4619.75,3459.75 v1(4630,3470) ; UD1.K12@4619.75,3532.12 4628.63,3541 v1(4633,3541) v1@4635.31,3543.31 ; UD1.H12@4619.75,3583.3 4631.21,3571.84 v1(4635.31,3571.84) ; UD1.D12@4619.75,3685.66 4626.74,3685.66 v1(4637.08,3696) 4645.08,3704 C17.2@4663,3704 ; C1.1@4664,3548.5 4640.5,3548.5 v1@4635.31,3543.31 ; C3.2@4664,3575 4661.43,3572.43 4635.9,3572.43 v1(4635.31,3571.84) ; U1.AC18@3675.76,3473.41 3661.84,3459.49 3661.84,3458.5 3673.3,3447.04 v1(3675.44,3447.04) 3675.44,3447.63 v1(3689.27,3461.46) ; U1.AC18@3675.76,3473.41 3687.7,3461.46 v1(3689.27,3461.46) ; v1(3689.27,3461.46) 3702.71,3474.9 v1(3704.12,3474.9) 3691.7,3487.32 3689.68,3487.32 3716.14,3513.79 v1(3716.14,3515.2) 3717.56,3515.2 U1.AC24@3759.28,3556.91 ; U1.W24@3703.6,3612.6 3717.51,3626.51 3730.76,3613.27 ; U1.W24@3703.6,3612.6 U1.Y24@3717.52,3598.68 ; U1.Y24@3717.52,3598.68 U1.AA24@3731.44,3584.76 ; U1.Y24@3717.52,3598.68 3730.76,3611.92 3730.76,3613.27 ; 3730.76,3613.27 3743.72,3600.31 v1(3743.72,3597.93) ; U1.AA24@3731.44,3584.76 U1.AB24@3745.36,3570.84 ; U1.AA24@3731.44,3584.76 3731.44,3585.65 v1(3743.72,3597.93) ; v1(3743.72,3597.93) v1(3757.86,3583.79) ; U1.AB24@3745.36,3570.84 3757.86,3583.34 v1(3757.86,3583.79) ; U1.AB24@3745.36,3570.84 U1.AC24@3759.28,3556.93 ; v1@4635.31,3543.31 v1(4635.31,3571.84)
  Bottom Layer w3: 4566,3585 4580,3585
  Bottom Layer w4.5: v1(3781.12,3604.84) 3781.28,3605 R3.2@3781.28,3630.28
  Bottom Layer w8: C16.2@4232,3683 4251.31,3683 v1(4253.97,3685.66) ; C14.1@4363.5,3801 4363.5,3786.2 v1(4367.5,3782.2)
  Bottom Layer w10: v1(4218,3616.16) 4224.5,3609.66 C19.1@4224.5,3598 ; 4304.55,3333.29 4317.37,3333.29 v1(4322.08,3338) ; C15.1@4316.5,3516 4316.5,3533.42 v1(4321.08,3538) ; v1(4349.94,3723.18) 4350.12,3723 C26.2@4373,3723 ; v1(4358.08,3209) 4370.37,3221.29 4388.71,3221.29 C21.2@4389,3221 ; v1(4411.21,3748.77) 4419.41,3756.97 R4.2@4434.71,3756.97 ; v1(4415.96,3698.37) 4438.63,3698.37 C25.2@4439,3698 ; v1(4422,3292) 4423,3291 C24.2@4443,3291 ; C20.2@4456.69,3406.29 4456.69,3405.39 v1(4476.08,3386) ; v1(4472.07,3627.03) 4489.09,3644.05 C23.2@4502.08,3644.05 ; v1(4475.09,3741.8) 4497.31,3741.8 R5.2@4501,3745.49 ; v1(4571,3473) 4576.37,3478.37 4576.37,3490.11 4574.77,3491.71 4575.45,3492.39 4575.45,3506.55 v1(4571,3511)
VDD18-DRAM: C6.1 C7.2 C27.1 C28.2 U1.AD25 | length 1188.1
  Top Layer w10: C27.1@4077.5,3673 4065,3673 v1(4051,3659) 4058,3652 C28.2@4078,3652 ; C6.1@4631.13,3824.87 4631.13,3812.13 v1(4630,3811) 4663,3778 C7.2@4663,3755
  Top Layer w12: U1.AD25@3786.79,3556.92 3798.45,3568.58 v1(3799.94,3568.58) ; v1(4204.26,3730) 4252.86,3778.6 4290.68,3778.6 v1(4298.08,3786)
  Inner2 w12: v1(3799.94,3568.58) 3829.06,3539.46 3846.04,3539.46 3870.08,3563.5 3876.5,3563.5 3948,3635 3991,3635 4006,3650 4042,3650 v1(4051,3659) 4060.5,3668.5 4088.5,3668.5 4103,3683 4194,3683 4204.26,3693.26 v1(4204.26,3730) ; v1(4298.08,3786) 4298.08,3786.52 4312.86,3801.3 4407.7,3801.3 4427,3782 4467,3782 4486.3,3801.3 4508.3,3801.3 4556,3849 4592,3849 v1(4630,3811)
VDD18-LPDDR: C8.1 C9.2 C10.2 C11.2 C12.2 C13.2 UD1.F1 UD1.F12 UD1.G4 UD1.G9 UD1.T4 UD1.T9 UD1.U1 UD1.U12 | length 1452.5
  Top Layer w4: UD1.T9@4525.26,3378.57 v1(4538.92,3392.23)
  Top Layer w10: UD1.F1@4273.29,3634.48 4273.67,3634.48 4288.08,3648.89 v1(4288.08,3651) ; UD1.T4@4367.77,3378.57 4383.99,3362.36 v1(4383.99,3362.06) ; UD1.G4@4367.78,3608.89 4371.97,3608.89 4384.62,3621.54 v1(4384.62,3625.73) ; v1(4510.23,3593.86) UD1.G9@4525.26,3608.89 ; UD1.U12@4619.75,3352.98 v1(4631.91,3365.13) 4644.78,3352.26 4659.74,3352.26 C11.2@4664,3348 ; UD1.F12@4619.75,3634.48 v1(4641,3634.48) 4656.52,3650 C9.2@4663,3650 ; C12.2@4664,3444 4655,3453 v1(4642,3453) 4642,3453.5 C8.1@4664,3475.5
  Top Layer w12: UD1.U1@4273.28,3352.98 4285.8,3365.49 v1(4288.56,3365.49)
  Inner2 w10: v1(4288.56,3365.49) 4380.56,3365.49 v1(4383.99,3362.06)
  Inner2 w12: v1(4288.08,3651) 4291.08,3654 4362.99,3654 4384.62,3632.37 v1(4384.62,3625.73) 4387.89,3629 4423.62,3629 4445.62,3607 4497.09,3607 v1(4510.23,3593.86) 4510.23,3594.08 4542.2,3626.05 4632.57,3626.05 v1(4641,3634.48) 4642,3634.48 4657,3619.48 4657,3531 4641,3515 v1(4638,3515) ; v1(4383.99,3362.06) 4383.99,3380.77 4411.22,3408 4523.15,3408 v1(4538.92,3392.23) 4576.86,3392.23 4603.95,3365.14 v1(4631.91,3365.13) 4627,3370.04 4627,3440.46 4639.54,3453 v1(4642,3453)
  Bottom Layer w8: v1(4288.56,3365.49) 4308.49,3365.49 C13.2@4309,3366
  Bottom Layer w10: C10.2@4275.17,3637.83 4275.17,3638.09 v1(4288.08,3651)
  Bottom Layer w12: v1(4638,3515) 4647.74,3515 4663.94,3498.8 4663.94,3474.94 v1(4642,3453)
pads on no net: U1.A2 U1.A3 U1.A4 U1.A5 U1.A6 U1.A8 U1.A10 U1.A12 U1.A14 U1.A16 U1.A18 U1.A20 U1.A22 U1.A24 U1.A26 U1.A28 U1.A29 U1.A30 U1.A31 U1.A32 U1.A33 U1.AA1 U1.AA2 U1.AA3 U1.AA4 U1.AA5 U1.AA6 U1.AA7 U1.AA9 U1.AA12 U1.AA13 U1.AA19 U1.AB2 U1.AB3 U1.AB9 U1.AB13 U1.AC2 U1.AC3 U1.AC4 U1.AC5 U1.AC6 U1.AC7 U1.AC9 U1.AC15 U1.AD1 U1.AD2 U1.AD15 U1.AE1 U1.AE2 U1.AE3 U1.AE4 U1.AE5 U1.AE6 U1.AE7 U1.AE11 U1.AE13 U1.AE16 U1.AF1 U1.AF2 U1.AG1 U1.AG2 U1.AG4 U1.AG5 U1.AG9 U1.AG13 U1.AG15 U1.AG17 U1.AH1 U1.AH2 U1.AH11 U1.AH13 U1.AH15 U1.AH17 U1.AJ1 U1.AJ2 U1.AJ3 U1.AJ4 U1.AJ5 U1.AJ7 U1.AJ9 U1.AJ11 U1.AJ15 U1.AJ17 U1.AK1 U1.AK2 U1.AK7 U1.AK9 U1.AK13 U1.AK15 U1.AK17 U1.AK33 U1.AL1 U1.AL2 U1.AL5 U1.AL7 U1.AL11 U1.AL15 U1.AL16 U1.AL17 U1.AL27 U1.AL32 U1.AL33 U1.AM1 U1.AM2 U1.AM3 U1.AM4 U1.AM6 U1.AM7 U1.AM8 U1.AM9 U1.AM10 U1.AM11 U1.AM12 U1.AM13 U1.AM14 U1.AM15 U1.AM16 U1.AM17 U1.AM18 U1.AM33 U1.AN2 U1.AN3 U1.AN4 U1.AN5 U1.AN6 U1.AN7 U1.AN8 U1.AN9 U1.AN13 U1.AN15 U1.AN17 U1.AN26 U1.B1 U1.B2 U1.B3 U1.B4 U1.B5 U1.B6 U1.B7 U1.B8 U1.B9 U1.B10 U1.B11 U1.B12 U1.B13 U1.B14 U1.B15 U1.B16 U1.B17 U1.B18 U1.B19 U1.B20 U1.B21 U1.B22 U1.B23 U1.B24 U1.B25 U1.B26 U1.B27 U1.B28 U1.B29 U1.B30 U1.B31 U1.B32 U1.B33 U1.C1 U1.C2 U1.C3 U1.C4 U1.C7 U1.C9 U1.C11 U1.C13 U1.C15 U1.C16 U1.C17 U1.C19 U1.C21 U1.C22 U1.C23 U1.C24 U1.C25 U1.C26 U1.C27 U1.C28 U1.C29 U1.C30 U1.C31 U1.C32 U1.C33 U1.D1 U1.D2 U1.D8 U1.D10 U1.D12 U1.D14 U1.D16 U1.D18 U1.D20 U1.D22 U1.D24 U1.D26 U1.D28 U1.D32 U1.D33 U1.E1 U1.E2 U1.E4 U1.E5 U1.E6 U1.E8 U1.E10 U1.E12 U1.E14 U1.E16 U1.E18 U1.E20 U1.E22 U1.E24 U1.E26 U1.E28 U1.E29 U1.E30 U1.E31 U1.E32 U1.E33 U1.F1 U1.F2 U1.F14 U1.F16 U1.F18 U1.F20 U1.F22 U1.F24 U1.F26 U1.F28 U1.F32 U1.F33 U1.G1 U1.G2 U1.G4 U1.G5 U1.G6 U1.G12 U1.G16 U1.G20 U1.G22 U1.G24 U1.G26 U1.G28 U1.G30 U1.G31 U1.G32 U1.G33 U1.H2 U1.H3 U1.H24 U1.H31 U1.H32 U1.J1 U1.J2 U1.J4 U1.J5 U1.J7 U1.J15 U1.J16 U1.J17 U1.J18 U1.J19 U1.J21 U1.J22 U1.J23 U1.J26 U1.J29 U1.J30 U1.J32 U1.J33 U1.K2 U1.K3 U1.K13 U1.K15 U1.K16 U1.K19 U1.K21 U1.K22 U1.K24 U1.K25 U1.K31 U1.K32 U1.L1 U1.L2 U1.L4 U1.L5 U1.L7 U1.L9 U1.L15 U1.L16 U1.L17 U1.L18 U1.L19 U1.L21 U1.L22 U1.L24 U1.L26 U1.L28 U1.L29 U1.L31 U1.L32 U1.M2 U1.M3 U1.M10 U1.M16 U1.M18 U1.M19 U1.M21 U1.M22 U1.M31 U1.M32 U1.N1 U1.N2 U1.N4 U1.N5 U1.N7 U1.N9 U1.N13 U1.N21 U1.N24 U1.N28 U1.N29 U1.N31 U1.N32 U1.N33 U1.P2 U1.P3 U1.P9 U1.P13 U1.P18 U1.P21 U1.P22 U1.P31 U1.P32 U1.R1 U1.R2 U1.R4 U1.R5 U1.R6 U1.R15 U1.R17 U1.R18 U1.R22 U1.R26 U1.R28 U1.R29 U1.R30 U1.R31 U1.R32 U1.R33 U1.T2 U1.T3 U1.T9 U1.T11 U1.T13 U1.T19 U1.T21 U1.T22 U1.T31 U1.T32 U1.U1 U1.U2 U1.U3 U1.U4 U1.U5 U1.U6 U1.U8 U1.U10 U1.U12 U1.U13 U1.U18 U1.U19 U1.U21 U1.U22 U1.U26 U1.U28 U1.U29 U1.U30 U1.U31 U1.U32 U1.U33 U1.V2 U1.V3 U1.V31 U1.V32 U1.W1 U1.W2 U1.W3 U1.W4 U1.W5 U1.W6 U1.W7 U1.W9 U1.W10 U1.W19 U1.W21 U1.W28 U1.W29 U1.W31 U1.W32 U1.W33 U1.Y2 U1.Y3 U1.Y9 U1.Y10 U1.Y12 U1.Y13 U1.Y19 U1.Y21 U1.Y31 U1.Y32 UD1.A1 UD1.A2 UD1.A11 UD1.A12 UD1.AA1 UD1.AA12 UD1.AB1 UD1.AB2 UD1.AB11 UD1.AB12 UD1.B1 UD1.B12 UD1.G11 UD1.K5 UD1.K8 UD1.N5 UD1.N8

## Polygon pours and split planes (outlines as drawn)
GND on Top Layer (solid, pour order 4): 3000,3000 4799,3000 4799,4055 3000,4055
GND on Bottom Layer (solid, pour order 8): 3000,3000 4799,3000 4799,4059.01 3000,4059.01
GND on Inner1 (solid): 3000,3000 4799,3000 4799,4053.77 3000,4053.77
GND on Inner2 (solid): 3000,3000 4799,3000 4799,4055 3000,4055
GND on Inner1 (solid): 3680,3637 3998,3955 4557,3955 4713,3799 4713,3183 4604,3074 3994,3074 3680,3388
VCC-DRAM on Bottom Layer (solid, pour order 4): 3683,3384 3683,3640 4001,3958 4558,3958 4715,3801 4715,3197 4590,3072 4002,3072 3690,3384

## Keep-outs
Top Layer:
  region: 3805,3370 3968,3533 3968,3537 3816,3689 3816,3721.79 4033.21,3939 4514.16,3939 4660.3,3792.86 4660.3,3209.3 4533,3082 4056.2,3082 3805,3333.2
Inner2:
  region: 3804.66,3370.14 3967.66,3533.14 3967.66,3537.14 3815.66,3689.14 3815.66,3721.93 4032.87,3939.14 4513.81,3939.14 4659.96,3793 4659.96,3209.44 4532.66,3082.14 4055.86,3082.14 3804.66,3333.34
Board Outline Layer:
  lines w10: 3000,3000 4799,3000 4799,4055 3000,4055 3000,3000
